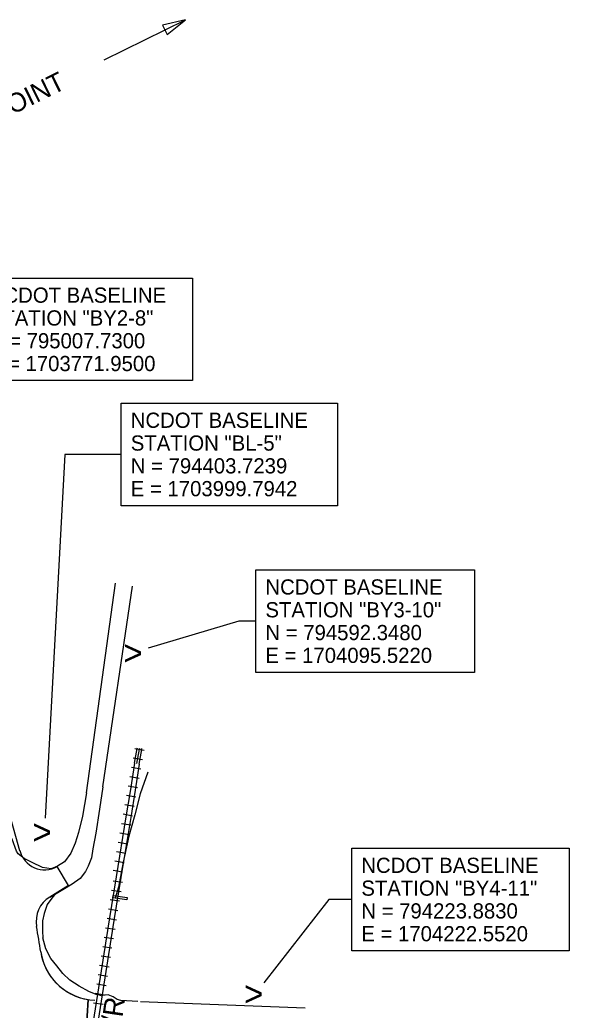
# Model space of a CAD drawing. Extents: x 1701144 to 1707001, y 793349 to 797175.
# Drawn here: x 1703974 to 1704552, y 794216 to 795259 of the extents above; entities that cross this region are included whole.
import ezdxf

# ---------------------------------------------------------------- set-up
doc = ezdxf.new("R2010")
doc.units = 0
for name, color, linetype in [('CTL Sheet Text', 7, 'Continuous'), ('Default', 7, 'Continuous'), ('Exist Property Titlesheet Border PSD CELL', 7, 'Continuous'), ('Old_Level_3', 7, 'Continuous'), ('Old_Level_5', 7, 'Continuous'), ('Old_Level_57', 7, 'Continuous'), ('Prop EOT', 7, 'Continuous'), ('Prop North Arrow NAD83 for Plan Sheets CELL', 7, 'Continuous'), ('Proposed Right of Way Monument PSD Leader', 7, 'Continuous'), ('Proposed Right of Way Monument PSD Text', 7, 'Continuous'), ('Sheet Title CELL', 7, 'Continuous')]:
    doc.layers.add(name, color=color, linetype=linetype)

msp = doc.modelspace()

# ---------------------------------------------------------------- linework, layer by layer
at = {"layer": 'CTL Sheet Text'}
msp.add_line((1704062.2, 795216.5), (1704147.9, 795258.6), dxfattribs=at)
msp.add_lwpolyline([(1704123.9, 795252.8), (1704128.6, 795243.2), (1704147.9, 795258.6)], close=True, dxfattribs=at)
at = {"layer": 'Default'}
for p, q in [((1704024.9, 794347.3), (1704012.7, 794367.2)), ((1704012.7, 794367.2), (1704012.7, 794367.2)), ((1704005, 794335.2), (1704024.9, 794347.3)), ((1704041.9, 794164.4), (1704045.6, 794227.2))]:
    msp.add_line(p, q, dxfattribs=at)
msp.add_lwpolyline([(1704096.9, 794475.6), (1704099.6, 794491), (1704099.8, 794491.8)], dxfattribs=at)
for centre, radius, start, end in [((1702989.1, 794124.6), 1018, 14.7589, 42.7091), ((1703999.6, 794390.9), 27, 194.7589, 298.9282), ((1704020.7, 794309.6), 30, 121.4124, 190.1653), ((1702989.1, 794124.6), 1018, 8.634, 10.1653), ((1704054.9, 794286.5), 60, 188.634, 261.1171)]:
    msp.add_arc(centre, radius, start, end, dxfattribs=at)
at = {"layer": 'Exist Property Titlesheet Border PSD CELL'}
for points in [[(1703930.9, 794986.8), (1704155.5, 794986.8), (1704155.5, 794878.8), (1703930.9, 794878.8)], [(1704080.4, 794855.1), (1704308, 794855.1), (1704308, 794747.1), (1704080.4, 794747.1)], [(1704222.2, 794679.6), (1704452.3, 794679.6), (1704452.3, 794571.6), (1704222.2, 794571.6)], [(1704323.2, 794386.6), (1704552.1, 794386.6), (1704552.1, 794278.6), (1704323.2, 794278.6)]]:
    msp.add_lwpolyline(points, close=True, dxfattribs=at)
at = {"layer": 'Old_Level_3'}
for p, q in [((1704043.7, 794444.9), (1704074.3, 794665.6)), ((1704061, 794451.2), (1704092.1, 794662.5)), ((1704100.8, 794225.4), (1704274.2, 794218.4))]:
    msp.add_line(p, q, dxfattribs=at)
for points in [[(1704061, 794451.2), (1704057.3, 794427.7), (1704053.5, 794402.5), (1704050.6, 794385.9), (1704048.9, 794376.6), (1704045.6, 794367.7), (1704042.6, 794362.1), (1704037.1, 794354.7), (1704028.5, 794348.6), (1704018.7, 794342.9), (1704010.2, 794337.6), (1704007.2, 794334.1), (1704002.5, 794327.4), (1703999.2, 794317.9), (1703997.5, 794310.2), (1703997.6, 794299.3), (1703997.9, 794292.1)], [(1704043.7, 794444.9), (1704039.7, 794420.4), (1704035.4, 794403), (1704031.7, 794391.8), (1704027.1, 794381.3), (1704020.5, 794372.2), (1704013.2, 794367.6), (1704006.7, 794365), (1703997.6, 794366.2), (1703986.4, 794371.5), (1703978, 794375.9), (1703971.9, 794380.8), (1703969.9, 794383.6), (1703965.5, 794396), (1703963.5, 794400.4)], [(1704056.9, 794232.1), (1704054.1, 794232.5), (1704046.1, 794235.8), (1704036, 794241.4), (1704026.1, 794247.6), (1704018.7, 794254.7), (1704012.5, 794262.8), (1704006.1, 794270.4), (1704001.1, 794280.7), (1703997.9, 794292.1)], [(1704056.9, 794232.1), (1704059.2, 794231.7)], [(1704097.7, 794225.3), (1704079.8, 794226.3), (1704076, 794227.2), (1704071.9, 794230.2), (1704066.7, 794232.1), (1704063.3, 794231.9), (1704059.2, 794231.7)]]:
    msp.add_lwpolyline(points, dxfattribs=at)
at = {"layer": 'Old_Level_5'}
for p, q in [((1704102.7, 794479.6), (1704092.8, 794481.4)), ((1704104.4, 794489.5), (1704094.6, 794491.2)), ((1704101, 794469.8), (1704091.1, 794471.5)), ((1704099.2, 794459.9), (1704089.4, 794461.7)), ((1704097.5, 794450.1), (1704087.6, 794451.8)), ((1704095.7, 794440.2), (1704085.9, 794442)), ((1704094, 794430.4), (1704084.2, 794432.1)), ((1704092.3, 794420.5), (1704082.4, 794422.3)), ((1704090.5, 794410.7), (1704080.7, 794412.4)), ((1704088.8, 794400.8), (1704078.9, 794402.6)), ((1704087.1, 794391), (1704077.2, 794392.7)), ((1704085.3, 794381.1), (1704075.5, 794382.9)), ((1704083.6, 794371.3), (1704073.7, 794373)), ((1704081.8, 794361.4), (1704072, 794363.2)), ((1704081.6, 794350.4), (1704071.8, 794352)), ((1704080.1, 794340.6), (1704070.2, 794342.1)), ((1704078.5, 794330.7), (1704068.6, 794332.2)), ((1704076.9, 794320.8), (1704067.1, 794322.4)), ((1704075.4, 794310.9), (1704065.5, 794312.5)), ((1704073.8, 794301.1), (1704063.9, 794302.6)), ((1704072.2, 794291.2), (1704062.3, 794292.7)), ((1704069.1, 794271.4), (1704059.2, 794273)), ((1704070.6, 794281.3), (1704060.8, 794282.9)), ((1704067.5, 794261.5), (1704057.6, 794263.1)), ((1704065.9, 794251.7), (1704056, 794253.2)), ((1704064.4, 794241.8), (1704054.5, 794243.4)), ((1704062.8, 794231.9), (1704052.9, 794233.5)), ((1704061.2, 794222), (1704051.3, 794223.6))]:
    msp.add_line(p, q, dxfattribs=at)
for points in [[(1704094.4, 794476), (1704097.2, 794491.4), (1704097.3, 794492.2)], [(1704099.4, 794475.1), (1704102.1, 794490.6), (1704102.2, 794491.5)], [(1704094.4, 794476), (1704090, 794448.4), (1704085.3, 794419.7), (1704075, 794356.6)], [(1704099.4, 794475.2), (1704095, 794447.6), (1704090.3, 794418.9), (1704080, 794355.7)], [(1704108.3, 794466.5), (1704100.3, 794443.7), (1704094.5, 794421.6), (1704088.5, 794399.2), (1704082.5, 794371.8)], [(1704082.5, 794371.8), (1704077.6, 794345.7), (1704074.1, 794334)], [(1704075, 794356.5), (1704067.8, 794311.2), (1704055.3, 794233.1), (1704038.7, 794129), (1704030.1, 794074.8)], [(1704080, 794355.8), (1704072.7, 794310.4), (1704060.2, 794232.3), (1704043.6, 794128.2), (1704035, 794074)]]:
    msp.add_lwpolyline(points, dxfattribs=at)
msp.add_lwpolyline([(1704086.2, 794332.2), (1704071.4, 794334.5), (1704071.7, 794336.8), (1704086.6, 794334.6)], close=True, dxfattribs=at)
at = {"layer": 'Prop EOT'}
for p, q in [((1704024.9, 794347.3), (1704012.7, 794367.2)), ((1704024.9, 794347.3), (1704005, 794335.2)), ((1704045.6, 794227.2), (1704041.9, 794163.8))]:
    msp.add_line(p, q, dxfattribs=at)
for centre, radius, start, end in [((1702989.1, 794124.6), 1018, 14.7589, 42.7091), ((1703999.6, 794390.9), 27, 194.7589, 299.2661), ((1704020.7, 794309.6), 30, 121.4124, 190.1653), ((1702989.1, 794124.6), 1018, 8.634, 10.1653), ((1704054.9, 794286.5), 60, 188.634, 267.7131)]:
    msp.add_arc(centre, radius, start, end, dxfattribs=at)
at = {"layer": 'Prop North Arrow NAD83 for Plan Sheets CELL'}
msp.add_line((1704256.3, 794796.2), (1704256.1, 794796.2), dxfattribs=at)
msp.add_line((1704256.3, 794796.2), (1704256.1, 794796.2), dxfattribs=at)
at = {"layer": 'Proposed Right of Way Monument PSD Leader'}
for points in [[(1704080.4, 794801.1), (1704020.8, 794801.1), (1704000.1, 794418.1)], [(1704222.2, 794625.6), (1704204.1, 794625.6), (1704108.7, 794597.2)], [(1704323.2, 794332.6), (1704299, 794332.6), (1704230.4, 794244.9)]]:
    msp.add_lwpolyline(points, dxfattribs=at)

# ---------------------------------------------------------------- texts
at = {"layer": 'CTL Sheet Text'}
msp.add_text('TO HIGH POINT', height=20, rotation=26.1672, dxfattribs=at).set_placement((1703843.1, 795098.2))
at = {"layer": 'Old_Level_57'}
for p in [(1704082.5, 794579.3), (1703986.8, 794390.7), (1704209.6, 794220.4)]:
    msp.add_text('>', height=26.1, rotation=0.0142, dxfattribs=at).set_placement(p)
at = {"layer": 'Proposed Right of Way Monument PSD Text'}
for s, p in [('NCDOT BASELINE', (1703940.9, 794960.8)), ('STATION "BY2-8"', (1703940.9, 794936.8)), ('N = 795007.7300', (1703940.9, 794912.8)), ('E = 1703771.9500', (1703940.9, 794888.8)), ('NCDOT BASELINE', (1704090.4, 794829.1)), ('STATION "BL-5"', (1704090.4, 794805.1)), ('N = 794403.7239', (1704090.4, 794781.1)), ('E = 1703999.7942', (1704090.4, 794757.1)), ('NCDOT BASELINE', (1704232.2, 794653.6)), ('STATION "BY3-10"', (1704232.2, 794629.6)), ('N = 794592.3480', (1704232.2, 794605.6)), ('E = 1704095.5220', (1704232.2, 794581.6)), ('NCDOT BASELINE', (1704333.2, 794360.6)), ('STATION "BY4-11"', (1704333.2, 794336.6)), ('N = 794223.8830', (1704333.2, 794312.6)), ('E = 1704222.5520', (1704333.2, 794288.6))]:
    msp.add_text(s, height=16, dxfattribs=at).set_placement(p)
at = {"layer": 'Sheet Title CELL'}
msp.add_text('CAROLINA NORTHWESTERN R/R', height=21.157, rotation=81.6993, dxfattribs=at).set_placement((1704019.4, 793781.8))

doc.saveas('drawing.dxf')
